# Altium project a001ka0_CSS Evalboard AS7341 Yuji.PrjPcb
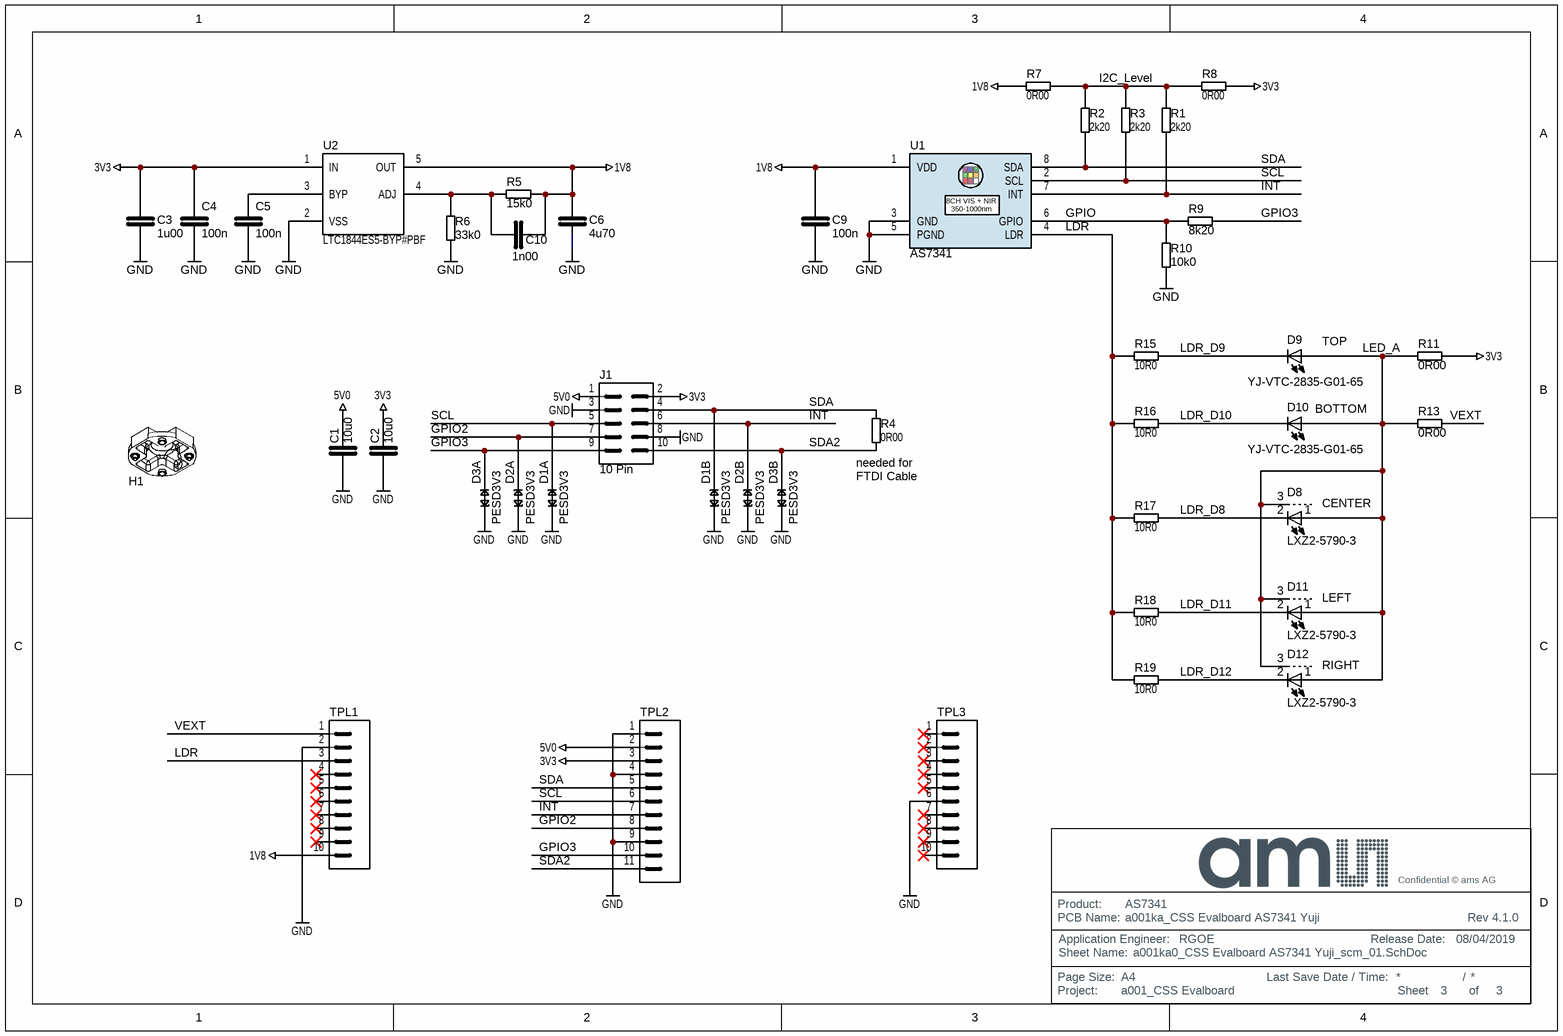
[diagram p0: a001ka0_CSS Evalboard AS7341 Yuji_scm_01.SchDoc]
ApplicationEngineer: RGOE; ARSProjectName: a001_CSS Evalboard; BoardtypeVersion: a001ka_CSS Evalboard AS7341 Yuji; ItemName: a001ka0_CSS Evalboard AS7341 Yuji; ProductNumber: AS7341; ReleaseDate: 08/04/2019; RevisionNumber: Rev 4.1.0; SupportingApplicationEngineer: FHAE; TotalNumberofSheets: 3
1 sheet, 40 parts. Net scope: global (net labels, ports and power ports of the same name join across sheets).
Board file: a001ka_CSS Evalboard AS7341 Yuji.PcbDoc

## Sheet a001ka0_CSS Evalboard AS7341 Yuji_scm_01.SchDoc
size A4; Organization: Altium Limited; Address1: L3, 12a Rodborough Rd; Address2: Frenchs Forest; Address3: NSW; Address4: Australia 2086; DocumentNumber: 9; SheetNumber: 3; SheetTotal: 3

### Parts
C1  10u0  [CAPC160x80x90L35L]
C2  10u0  [CAPC160x80x90L35L]
C3  1u00  [RESC1005X04L]
C4  100n  [CAPC100X50X55L25L]
C5  100n  [CAPC100X50X55L25L]
C6  4u70  [RESC1005X04L]
C9  100n  [CAPC100X50X55L25L]
C10  1n00  [CAPC100X50X55L25L]
D1  PESD3V3  [SOT23-3L]  (parts A,B of 2)
D2  PESD3V3  [SOT23-3L]  (parts A,B of 2)
D3  PESD3V3  [SOT23-3L]  (parts A,B of 2)
D8  LXZ2-5790-3  [LUXEON Z ES - w/o Paste]
D9  YJ-VTC-2835-G01-65  [YJ-VTC-2835-G01]
D10  YJ-VTC-2835-G01-65  [YJ-VTC-2835-G01]
D11  LXZ2-5790-3  [LUXEON Z ES - w/o Paste]
D12  LXZ2-5790-3  [LUXEON Z ES - w/o Paste]
H1  Reflective Adptr empty  [a001ga0_Reflective Adptr empty]  (value not drawn)
J1  10 Pin  [61201020621]
R1  2k20  [RESC155X80X55L30N]
R2  2k20  [RESC155X80X55L30N]
R3  2k20  [RESC155X80X55L30N]
R4  0R00  [RESC155X80X55L30N]
R5  15k0  [RESC100X50X40L22L]
R6  33k0  [RESC100X50X40L22L]
R7  0R00  [RESC155X80X55L30N]
R8  0R00  [RESC155X80X55L30N]
R9  8k20  [RESC100X50X40L22L]
R10  10k0  [RESC100X50X40L22L]
R11  0R00  [RESC155X80X55L30L]
R13  0R00  [RESC155X80X55L30L]
R15  10R0  [RESC155X80X55L30N]
R16  10R0  [RESC155X80X55L30N]
R17  10R0  [RESC155X80X55L30N]
R18  10R0  [RESC155X80X55L30N]
R19  10R0  [RESC155X80X55L30N]
TPL1  TestPoints  [TP DK 1mm - 10 Pos]  (value not drawn)  (no BOM)
TPL2  TestPoints  [TP DK 1mm - 11 Pos]  (value not drawn)  (no BOM)
TPL3  TestPoints  [TP DK 1mm - 10 Pos]  (value not drawn)  (no BOM)
U1  AS7341  [LGA8C80P2X4_200X310X110]
U2  LTC1844ES5-BYP#PBF  [SOT95P280X100-5L]

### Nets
1V8: C6.2 C9.2 C10.1 R5.2 R7.1 TPL1.10 U1.1(VDD) U2.5(OUT)
3V3: C2.2 C3.2 C4.2 J1.2 R8.2 R11.1 TPL2.3 U2.1(IN)
5V0: C1.2 J1.1 TPL2.2
GND: C1.1 C2.1 C3.1 C4.1 C5.1 C6.1 C9.1 D1.3(K) D2.3(K) D3.3(K) J1.3 J1.8 R6.1 R10.1 TPL1.2 TPL2.1 TPL2.4 TPL2.9 TPL3.6 U1.3(GND) U1.5(PGND) U2.2(VSS)
GPIO: R9.1 R10.2 U1.6(GPIO)
GPIO2: D2.1(A1) J1.7 TPL2.8
GPIO3: D3.1(A1) J1.9 R9.2 TPL2.10
I2C_Level: R1.2 R2.1 R3.1 R7.2 R8.1
INT: D2.2(A2) J1.6 R1.1 TPL2.7 U1.7(INT)
LDR: R15.1 R16.1 R17.1 R18.1 R19.1 TPL1.3 U1.4(LDR)
LDR_D8: D8.2(K) R17.2
LDR_D9: D9.1 R15.2
LDR_D10: D10.1 R16.2
LDR_D11: D11.2(K) R18.2
LDR_D12: D12.2(K) R19.2
LED_A: D8.1(A) D8.3(S) D9.2 D10.2 D11.1(A) D11.3(S) D12.1(A) D12.3(S) R11.2 R13.2
SCL: D1.1(A1) J1.5 R3.2 TPL2.6 U1.2(SCL)
SDA: D1.2(A2) J1.4 R2.2 R4.1 TPL2.5 U1.8(SDA)
SDA2: D3.2(A2) J1.10 R4.2 TPL2.11
VEXT: R13.1 TPL1.1
NetC5_2: C5.2 U2.3(BYP)
NetC10_2: C10.2 R5.1 R6.2 U2.4(ADJ)

Not connected (* = marked no-connect by the designer): TPL1 4* 5* 6* 7* 8* 9*; TPL3 1* 2* 3* 4* 5* 7* 8* 9* 10*

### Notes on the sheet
- (near D9) TOP
- (near D10) BOTTOM
- (near R4) needed for
- (near R4) FTDI Cable
- (near D8) CENTER
- (near D11) LEFT
- (near D12) RIGHT

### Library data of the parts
C1 C2 = 10056: CAP CER 10u0 10% 25V 1608 X5R; Manufacturer 1: Murata; Manufacturer Part Number 1: GRT188R61E106ME13D; Device: 10056
C3 = 1µ/10V/1005: 1µF ±20% 10V Ceramic Capacitor X5R 0402 (1005 Metric)
C4 C5 C9 = 10109: CAP CER 100n 10% 50V 1005 X7R; Manufacturer 1: Murata; Manufacturer Part Number 1: GCM155R71H104KE02D; Device: 10109
C6 = 4µ7/10V/1005: 4.7µF ±20% 10V Ceramic Capacitor X5R 0402 (1005 Metric)
C10 = 10097: CAP CER 1n00 10% 50V 1005 X7R; Manufacturer 1: Murata; Manufacturer Part Number 1: GCM155R71H102KA37D; Device: 10097
D1-D3 = PESD3V3L2BT,215: 26V Clamp 15A (8/20µs) Ipp Tvs Diode Surface Mount TO-236AB
D8 D11 D12 = LXZ2-5790-3: High Power LEDs - White Cool White, 5700K 3-Step, 90 CRI
D9 D10 = YJ-VTC-2835-G01-65: VTC Series High CRI LED SMD - 2835; Manufacturer 1: yujiintl.com
H1 = a001ga0_CSS Evalboard Reflective Adptr empty
J1 = WE_61201020621: 10 Positions Header Connector 0.100" (2.54mm) Surface Mount Gold
R1-R3 = 20180: RES SMD 2k20 1% 0.100W 1608 100ppm; Manufacturer 1: Panasonic; Manufacturer Part Number 1: ERJ-3EKF2201V; Device: 20180
R4 R7 R8 R11 R13 = 20123: RES SMD 0R00 1608; Manufacturer 1: Panasonic; Manufacturer Part Number 1: ERJ-3GEY0R00V; Device: 20123
R5 = 20078: RES SMD 15k0 1% 0.063W 1005 100ppm; Manufacturer 1: Vishay; Manufacturer Part Number 1: CRCW040215K0FKED; Device: 20078
R6 = 20086: RES SMD 33k0 1% 0.063W 1005 100ppm; Manufacturer 1: Vishay; Manufacturer Part Number 1: CRCW040233K0FKED; Device: 20086
R9 = 20072: RES SMD 8k20 1% 0.063W 1005 100ppm; Manufacturer 1: Vishay; Manufacturer Part Number 1: CRCW04028K20FKED; Device: 20072
R10 = 20074: RES SMD 10k0 1% 0.063W 1005 100ppm; Manufacturer 1: Vishay; Manufacturer Part Number 1: CRCW040210K0FKED; Device: 20074
R15-R19 = 20124: RES SMD 10R0 1% 0.100W 1608 100ppm; Manufacturer 1: Panasonic; Manufacturer Part Number 1: ERJ-3EKF10R0V; Device: 20124
TPL1 TPL3 = TP Row 10Pin: 1mm, 2,54mm Pitch
TPL2 = TP Row 11Pin: 1mm, 2,54mm Pitch
U1 = AS7341: 11-channel spectral sensor frontend; Manufacturer 1: ams; Manufacturer Part Number 1: 505670007
U2 = LTC1844ES5-BYP#TRMPBF: Linear Voltage Regulator IC Positive Adjustable Output 1.25 V ~ 6 V 150mA TSOT-23-5; Device: 3

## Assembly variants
Variant standard: not fitted D8 D10 D11 D12 H1 R7 R13
Variant Yuji 2x: not fitted D8 D11 D12 H1 R7 R13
